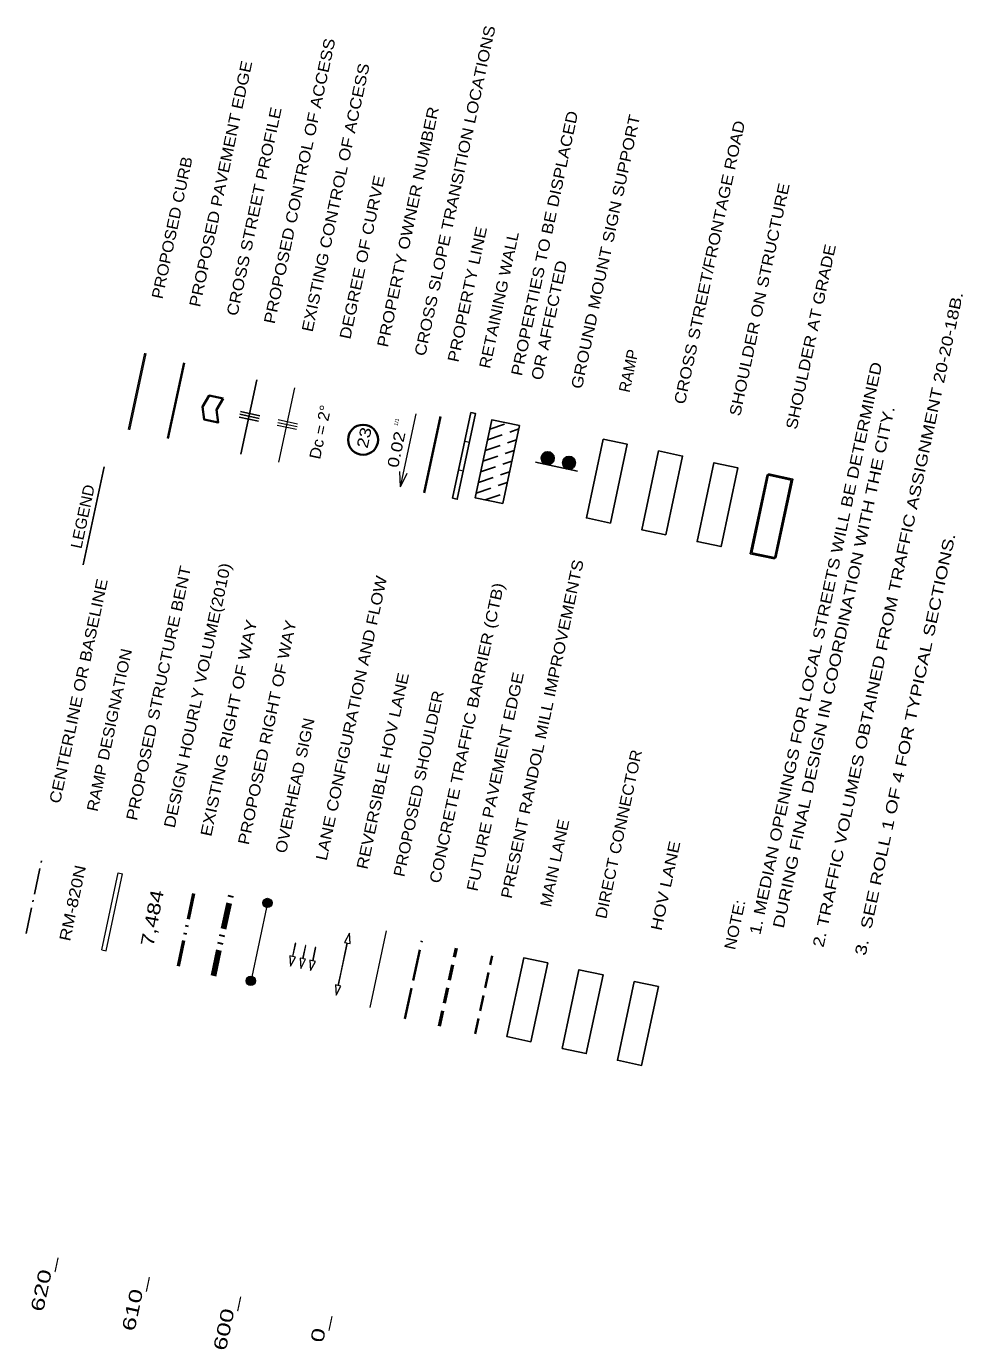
# Model space of a CAD drawing. Extents: x 2363411 to 2369702, y 6977197 to 6988655.
# Drawn here: x 2367341 to 2368344, y 6985397 to 6986795 of the extents above; entities that cross this region are included whole.
import ezdxf
from ezdxf.enums import TextEntityAlignment as Align

# ---------------------------------------------------------------- set-up
doc = ezdxf.new("R2010")
doc.units = 0
doc.header["$LTSCALE"] = 5.6
for name, pattern in [('DASH_DOUBLE_DOT', [9.2, 5, -1.2, 0.3, -1.2, 0.3, -1.2]), ('DOT_DASHED', [7.7, 5, -1.2, 0.3, -1.2]), ('LONG_DASHED', [7.5, 6, -1.5]), ('MEDIUM_DASHED', [4.5, 3, -1.5])]:
    doc.linetypes.add(name, pattern=pattern)
for name, color, linetype, lineweight in [('1', 7, 'Continuous', 25), ('13', 7, 'Continuous', 13), ('14', 7, 'Continuous', 13), ('2', 7, 'LONG_DASHED', 35), ('3', 7, 'Continuous', 13), ('44', 7, 'Continuous', 25), ('5', 7, 'MEDIUM_DASHED', 53), ('62', 7, 'Continuous', 25)]:
    doc.layers.add(name, color=color, linetype=linetype, lineweight=lineweight)

msp = doc.modelspace()

# ---------------------------------------------------------------- hatches: boundary and pattern name
at = {"layer": '3'}
for points in [[(2367900.966, 6986339.424, 1), (2367898.066, 6986325.85, 1)], [(2367923.721, 6986334.561, 1), (2367920.821, 6986320.987, 1)], [(2367600.358, 6985861.605, 1), (2367598.268, 6985851.825, 1)], [(2367582.458, 6985778.199, 1), (2367580.369, 6985768.419, 1)]]:
    msp.add_hatch(color=256, dxfattribs=at).paths.add_polyline_path(points)

# ---------------------------------------------------------------- linework, layer by layer
at = {"layer": '1', "linetype": 'MEDIUM_DASHED'}
for p, q in [((2367834.982, 6986352.353), (2367868.382, 6986363.969)), ((2367837.423, 6986363.79), (2367856.148, 6986370.302)), ((2367832.542, 6986340.919), (2367865.94, 6986352.531)), ((2367827.659, 6986318.044), (2367861.056, 6986329.657)), ((2367830.1, 6986329.48), (2367863.498, 6986341.093)), ((2367825.218, 6986306.607), (2367858.614, 6986318.219)), ((2367822.777, 6986295.17), (2367856.172, 6986306.782)), ((2367832.656, 6986288.016), (2367853.729, 6986295.343))]:
    msp.add_line(p, q, dxfattribs=at)
at = {"layer": '1', "linetype": 'DASH_DOUBLE_DOT', "lineweight": 53}
msp.add_line((2367504.008, 6985789.139), (2367521.639, 6985871.654), dxfattribs=at)
at = {"layer": '1'}
for points in [[(2367797.684, 6986289.838), (2367817.276, 6986381.528), (2367822.166, 6986380.483), (2367802.574, 6986288.793)], [(2367851.363, 6986284.26), (2367821.747, 6986290.345), (2367839.542, 6986373.716), (2367869.163, 6986367.627)], [(2368025.932, 6986250.71), (2368043.926, 6986334.924), (2368018.185, 6986340.424), (2368000.191, 6986256.21)]]:
    msp.add_lwpolyline(points, close=True, dxfattribs=at)
at = {"layer": '14'}
for points in [[(2367629.028, 6985813.643), (2367626.006, 6985799.496), (2367623.327, 6985800.069), (2367624.113, 6985788.992), (2367629.267, 6985798.799), (2367626.678, 6985799.353), (2367629.7, 6985813.499)], [(2367639.914, 6985811.317), (2367636.891, 6985797.17), (2367634.213, 6985797.743), (2367634.999, 6985786.666), (2367640.153, 6985796.473), (2367637.564, 6985797.027), (2367640.586, 6985811.173)], [(2367678.443, 6985782.435), (2367685.163, 6985813.88), (2367687.842, 6985813.308), (2367687.055, 6985824.383), (2367681.901, 6985814.576), (2367684.491, 6985814.024), (2367677.771, 6985782.578)], [(2367650.46, 6985809.063), (2367647.437, 6985794.917), (2367644.758, 6985795.489), (2367645.544, 6985784.413), (2367650.699, 6985794.222), (2367648.109, 6985794.773), (2367651.132, 6985808.92)], [(2367677.771, 6985782.578), (2367674.748, 6985768.432), (2367672.069, 6985769.004), (2367672.856, 6985757.927), (2367678.01, 6985767.736), (2367675.42, 6985768.288), (2367678.443, 6985782.435)]]:
    msp.add_lwpolyline(points, close=True, dxfattribs=at)
at = {"layer": '2'}
msp.add_line((2367746.584, 6985732.865), (2367764.735, 6985816.2), dxfattribs=at)
at = {"layer": '2', "linetype": 'MEDIUM_DASHED'}
msp.add_line((2367821.862, 6985716.78), (2367840.013, 6985800.115), dxfattribs=at)
at = {"layer": '3'}
for p, q in [((2367450.41, 6986363.531), (2367467.867, 6986445.234)), ((2367451.877, 6986363.217), (2367469.334, 6986444.921)), ((2367467.706, 6986444.481), (2367467.547, 6986443.738)), ((2367611.505, 6986328.476), (2367628.48, 6986407.92)), ((2367610.302, 6986371.04), (2367631.007, 6986366.616)), ((2367610.929, 6986373.974), (2367631.634, 6986369.55)), ((2367741.753, 6986301.965), (2367758.458, 6986380.148)), ((2367797.684, 6986289.838), (2367817.242, 6986381.532)), ((2367802.587, 6986288.792), (2367822.146, 6986380.486)), ((2367817.262, 6986381.529), (2367822.166, 6986380.483)), ((2367609.675, 6986368.106), (2367630.38, 6986363.683)), ((2367810.743, 6986350.964), (2367815.646, 6986349.917)), ((2367741.753, 6986301.965), (2367741.099, 6986318.529)), ((2367741.753, 6986301.965), (2367749.119, 6986316.815)), ((2367804.219, 6986320.399), (2367809.123, 6986319.353)), ((2367797.699, 6986289.833), (2367802.602, 6986288.787)), ((2367421.947, 6985806.55), (2367439.563, 6985888.997)), ((2367426.446, 6985805.589), (2367444.062, 6985888.036)), ((2367439.563, 6985888.997), (2367444.062, 6985888.036)), ((2367599.314, 6985856.714), (2367581.376, 6985772.761)), ((2367709.418, 6985745.032), (2367726.875, 6985826.735)), ((2367421.947, 6985806.55), (2367426.446, 6985805.589))]:
    msp.add_line(p, q, dxfattribs=at)
at = {"layer": '3', "lineweight": 35}
for p, q in [((2367510.052, 6986434.656), (2367492.755, 6986353.705)), ((2367767.336, 6986295.813), (2367784.794, 6986377.517))]:
    msp.add_line(p, q, dxfattribs=at)
at = {"layer": '3', "lineweight": 25}
for p, q in [((2367570.945, 6986337.142), (2367587.92, 6986416.586)), ((2367569.115, 6986376.773), (2367589.82, 6986372.349)), ((2367569.742, 6986379.707), (2367590.446, 6986375.283)), ((2367570.369, 6986382.641), (2367591.073, 6986378.217)), ((2367401.939, 6986218.722), (2367424.303, 6986323.39)), ((2367886.462, 6986328.455), (2367931.49, 6986318.834))]:
    msp.add_line(p, q, dxfattribs=at)
at = {"layer": '3', "linetype": 'DOT_DASHED', "lineweight": 25}
msp.add_line((2367340.858, 6985823.999), (2367358.489, 6985906.514), dxfattribs=at)
at = {"layer": '3', "linetype": 'DASH_DOUBLE_DOT', "lineweight": 90}
msp.add_line((2367541.582, 6985778.759), (2367560.609, 6985867.807), dxfattribs=at)
at = {"layer": '3', "lineweight": 35}
msp.add_lwpolyline([(2367551.998, 6986396.588), (2367544.806, 6986384.657), (2367546.495, 6986370.837), (2367531.571, 6986374.026), (2367529.881, 6986387.846), (2367537.073, 6986399.777)], close=True, dxfattribs=at)
msp.add_circle((2367701.724, 6986352.43), 16.098, dxfattribs=at)
at = {"layer": '3', "lineweight": 25}
for centre in [(2367899.516, 6986332.637), (2367922.271, 6986327.774)]:
    msp.add_circle(centre, 6.94, dxfattribs=at)
at = {"layer": '3'}
for centre in [(2367599.313, 6985856.715), (2367581.413, 6985773.309)]:
    msp.add_circle(centre, 5, dxfattribs=at)
at = {"layer": '5'}
msp.add_line((2367783.566, 6985724.963), (2367801.717, 6985808.298), dxfattribs=at)
at = {"layer": '62'}
for points in [[(2367940.952, 6986268.868), (2367958.946, 6986353.082), (2367984.687, 6986347.582), (2367966.694, 6986263.368)], [(2367966.694, 6986263.368), (2367984.687, 6986347.582), (2367958.946, 6986353.082), (2367940.952, 6986268.868)], [(2368000.191, 6986256.21), (2368018.185, 6986340.424), (2368043.926, 6986334.924), (2368025.932, 6986250.71)], [(2368059.43, 6986243.553), (2368077.423, 6986327.767), (2368103.165, 6986322.267), (2368085.171, 6986238.053)], [(2368085.171, 6986238.053), (2368103.165, 6986322.267), (2368077.423, 6986327.767), (2368059.43, 6986243.553)], [(2368116.469, 6986230.546), (2368134.462, 6986314.76), (2368160.204, 6986309.26), (2368142.21, 6986225.046)], [(2368118.092, 6986231.597), (2368136.086, 6986315.811), (2368161.827, 6986310.311), (2368143.833, 6986226.097)], [(2367855.744, 6985713.766), (2367873.737, 6985797.98), (2367899.479, 6985792.48), (2367881.485, 6985708.266)], [(2367881.485, 6985708.266), (2367899.479, 6985792.48), (2367873.737, 6985797.98), (2367855.744, 6985713.766)], [(2367914.982, 6985701.109), (2367932.976, 6985785.323), (2367958.717, 6985779.823), (2367940.723, 6985695.609)], [(2367940.723, 6985695.609), (2367958.717, 6985779.823), (2367932.976, 6985785.323), (2367914.982, 6985701.109)], [(2367974.221, 6985688.452), (2367992.215, 6985772.666), (2368017.956, 6985767.166), (2367999.962, 6985682.952)], [(2367999.962, 6985682.952), (2368017.956, 6985767.166), (2367992.215, 6985772.666), (2367974.221, 6985688.452)]]:
    msp.add_lwpolyline(points, close=True, dxfattribs=at)

# ---------------------------------------------------------------- texts
at = {"layer": '13', "width": 1.3}
msp.add_text('7,484', height=14, rotation=79.221, dxfattribs=at).set_placement((2367477.045, 6985809.393))
at = {"layer": '3'}
for s, width, p in [('CROSS SLOPE TRANSITION LOCATIONS', 1.15, (2367768.301, 6986441.296)), ('PROPOSED CONTROL OF ACCESS', 1.15, (2367607.024, 6986475.755)), ('PROPOSED PAVEMENT EDGE', 1.15, (2367527.057, 6986493.763)), ('EXISTING CONTROL OF ACCESS', 1.15, (2367647.584, 6986467.089)), ('CROSS STREET PROFILE', 1.15, (2367567.114, 6986484.283)), ('PROPERTY OWNER NUMBER', 1.15, (2367728.241, 6986450.715)), ('PROPERTIES TO BE DISPLACED', 1.15, (2367871.772, 6986420.047)), ('GROUND MOUNT SIGN SUPPORT', 1.15, (2367936.037, 6986406.121)), ('PROPOSED CURB', 1.1, (2367486.834, 6986502.419)), ('DEGREE OF CURVE', 1.15, (2367687.996, 6986459.314)), ('PROPERTY LINE', 1.15, (2367803.761, 6986434.702)), ('RETAINING WALL', 1.1, (2367837.578, 6986427.978)), ('OR AFFECTED', 1.15, (2367893.288, 6986415.45)), ('Dc = 2°', 1.1, (2367655.608, 6986330.803)), ('23', 1.25, (2367706.449, 6986342.5)), ('0.02', 1.25, (2367739.138, 6986321.75)), ('LEGEND', 1.05, (2367400.093, 6986235.163)), ('PROPOSED STRUCTURE BENT', 1.15, (2367459.52, 6985944.201)), ('DESIGN HOURLY VOLUME(2010)', 1.15, (2367499.905, 6985936.257)), ('PRESENT RANDOL MILL IMPROVEMENTS', 1.15, (2367860.812, 6985860.651)), ('CENTERLINE OR BASELINE', 1.15, (2367377.215, 6985962.472)), ('LANE CONFIGURATION AND FLOW', 1.15, (2367662.661, 6985901.349)), ('CONCRETE TRAFFIC BARRIER (CTB)', 1.15, (2367784.318, 6985876.996)), ('EXISTING RIGHT OF WAY', 1.2, (2367539.078, 6985927.141)), ('PROPOSED RIGHT OF WAY', 1.15, (2367579.239, 6985918.192)), ('RAMP DESIGNATION', 1.1, (2367417.333, 6985953.839)), ('REVERSIBLE HOV LANE', 1.15, (2367706.244, 6985892.036)), ('FUTURE PAVEMENT EDGE', 1.15, (2367824.181, 6985868.478)), ('PROPOSED SHOULDER', 1.1, (2367745.842, 6985883.92)), ('OVERHEAD SIGN', 1.1, (2367619.214, 6985909.275)), ('RM-820N', 1.2, (2367387.9, 6985815.083))]:
    msp.add_text(s, height=12, rotation=77.939, dxfattribs=dict(at, width=width)).set_placement(p)
msp.add_text('1/1', height=4.18, rotation=77.939, dxfattribs=at).set_placement((2367738.784, 6986367.048))
at = {"layer": '44', "width": 1.45}
for s, p in [('  620_', (2367371.704, 6985477.532)), ('  610_', (2367469.5, 6985456.636)), ('  600_', (2367567.298, 6985435.739)), ('  590_', (2367665.094, 6985414.843))]:
    msp.add_text(s, height=14, rotation=77.939, dxfattribs=at).set_placement(p, align=Align.RIGHT)
at = {"layer": '62'}
for s, width, p in [('CROSS STREET/FRONTAGE ROAD', 1.15, (2368046.346, 6986389.681)), ('SHOULDER ON STRUCTURE', 1.15, (2368105.584, 6986377.023)), ('SHOULDER AT GRADE', 1.15, (2368166.095, 6986362.712)), ('    2. TRAFFIC VOLUMES OBTAINED FROM TRAFFIC ASSIGNMENT 20-20-18B.', 1.25, (2368190.105, 6985786.638)), ('    1. MEDIAN OPENINGS FOR LOCAL STREETS WILL BE DETERMINED', 1.2, (2368122.625, 6985801.057)), ('      DURING FINAL DESIGN IN COORDINATION WITH THE CITY.', 1.25, (2368145.118, 6985796.251)), ('    3.  SEE ROLL 1 OF 4 FOR TYPICAL SECTIONS.', 1.3, (2368235.091, 6985777.026)), ('DIRECT CONNECTOR', 1.1, (2367962.083, 6985839.013)), ('MAIN LANE', 1.1, (2367902.844, 6985851.67)), ('HOV LANE', 1.2, (2368021.321, 6985826.355)), ('NOTE:', 1.1, (2368100.132, 6985805.863))]:
    msp.add_text(s, height=12, rotation=77.939, dxfattribs=dict(at, width=width)).set_placement(p)
msp.add_text('RAMP', height=12, rotation=77.939, dxfattribs=at).set_placement((2367987.107, 6986402.338))

doc.saveas('drawing.dxf')
